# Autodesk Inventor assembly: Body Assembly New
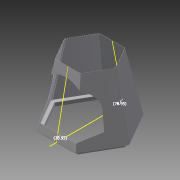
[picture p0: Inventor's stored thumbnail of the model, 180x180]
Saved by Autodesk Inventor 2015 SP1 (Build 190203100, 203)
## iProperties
Created: 2013-06
Part Number: Body Assembly New
Document SubType Name: Assembly
Designer: BarryWSUK
Author: BarryWSUK
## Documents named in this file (3)
- \\psf\Home\Documents\Inventor\Sau Paulo Chimnea\Body Assembly New.iam
- \\psf\Home\Documents\Inventor\Sau Paulo Chimnea\Body Part B.ipt
- \\psf\Home\Documents\Inventor\Sau Paulo Chimnea\Body Part A New.ipt
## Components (2 placed, 2 different names)
1. Body Part A New:1 — Mate:1, Mate:2, Flush:1
2. Body Part B:1 — Mate:1, Mate:2, Flush:1
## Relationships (3: Mate 2, Flush 1)
- Mate:1: Body Part A New:1 ↔ Body Part B:1
- Mate:2: Body Part A New:1 ↔ Body Part B:1
- Flush:1: Body Part A New:1 ↔ Body Part B:1
